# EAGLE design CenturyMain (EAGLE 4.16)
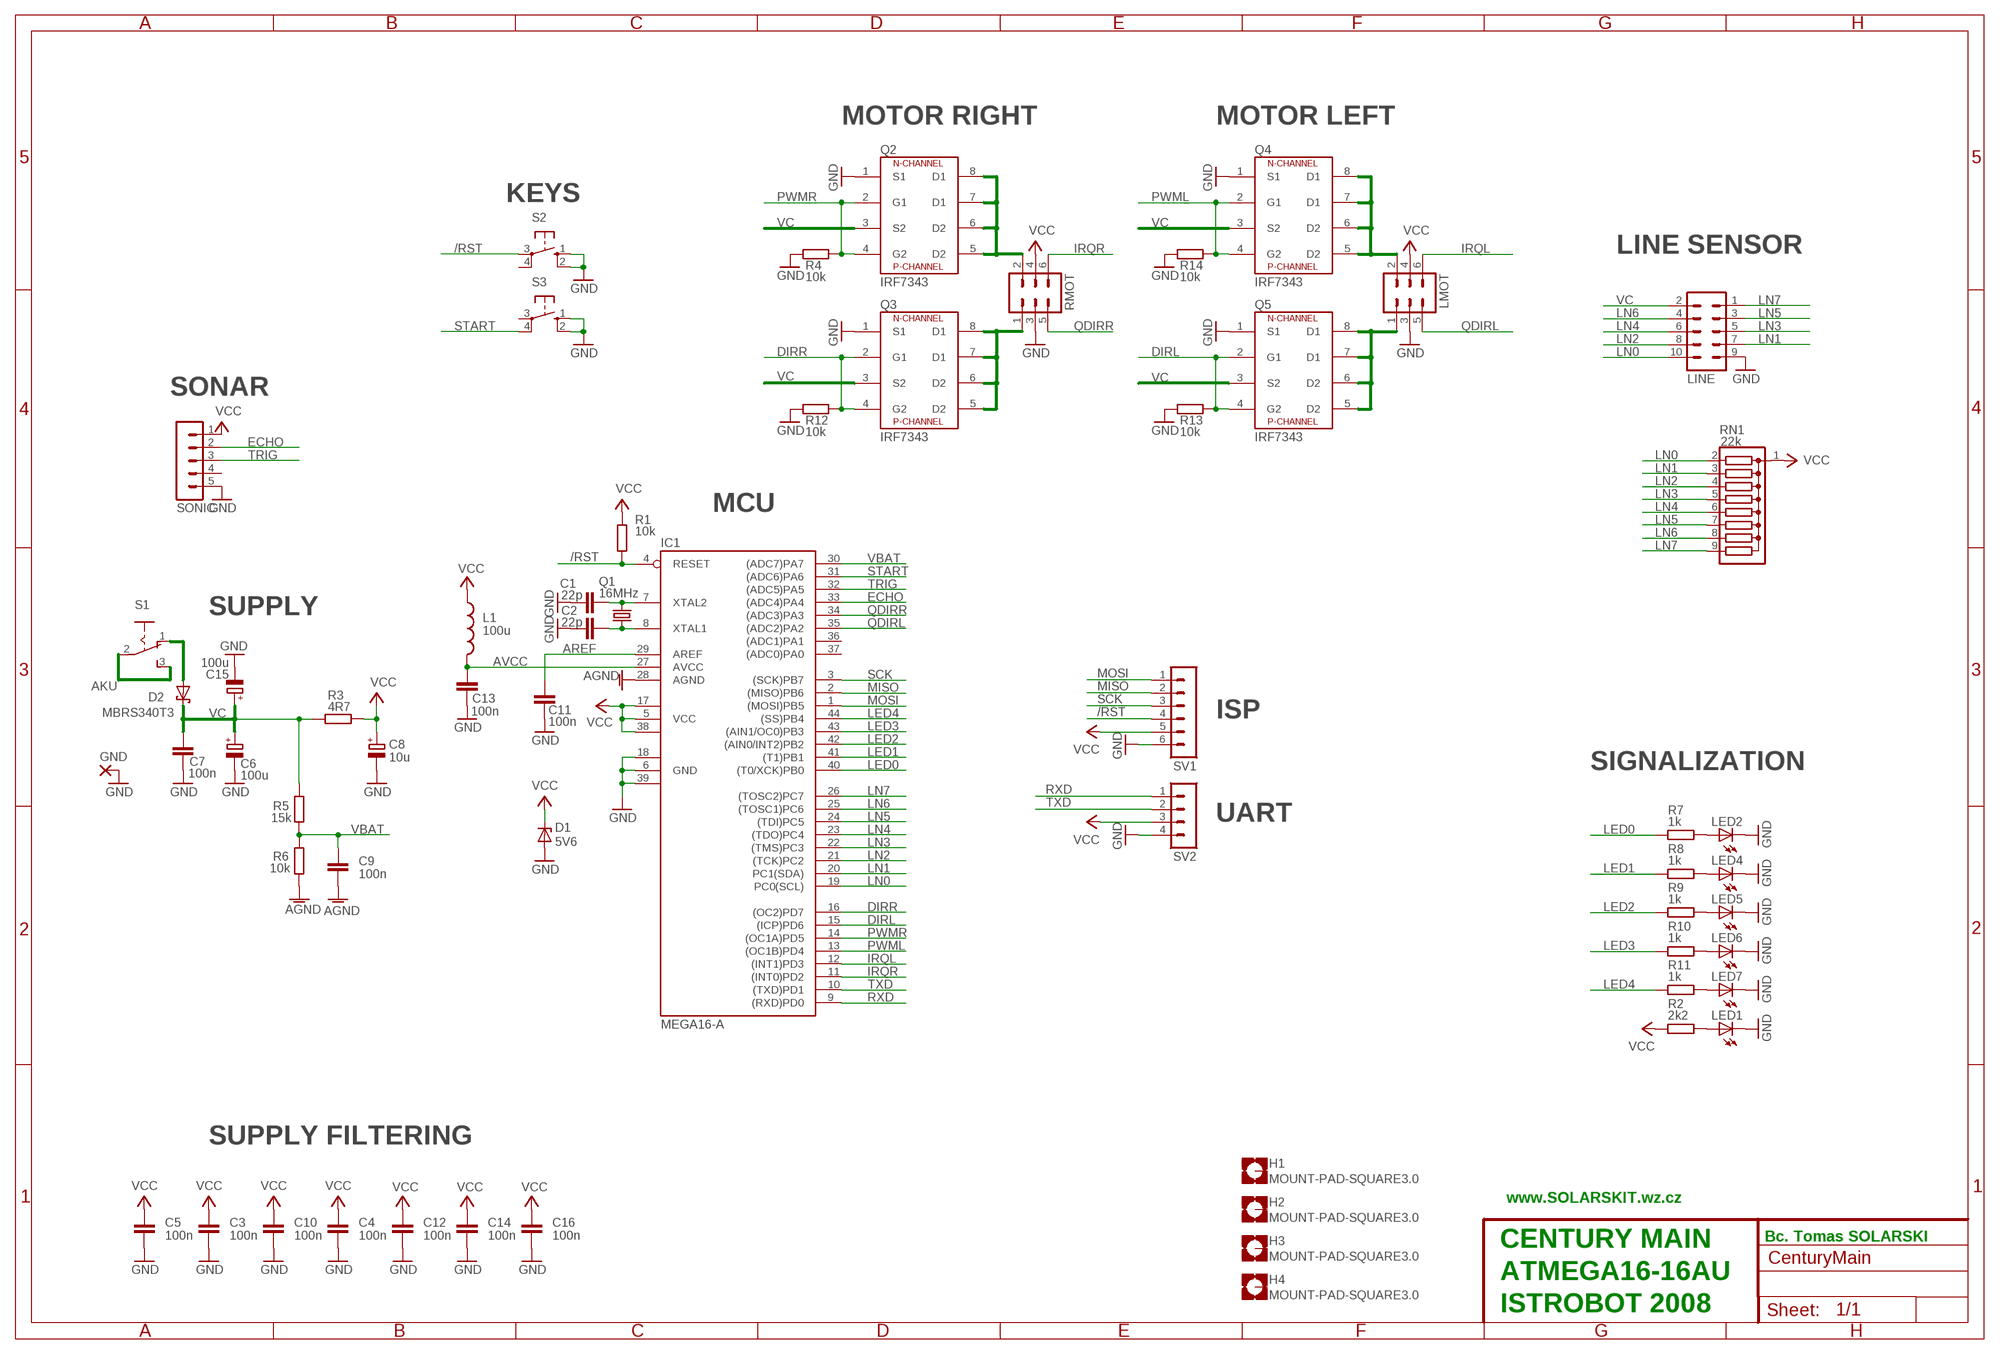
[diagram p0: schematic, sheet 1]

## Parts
C1  22p  C-EUC1206  [C1206]
C2  22p  C-EUC1206  [C1206]
C3  100n  C-EUC1206  [C1206]
C4  100n  C-EUC1206  [C1206]
C5  100n  C-EUC1206  [C1206]
C6  100u  CPOL-EUE5-8.5  [E5-8,5]
C7  100n  C-EUC1206  [C1206]
C8  10u  CPOL-EUB/3528-21W  [B/3528-21W]
C9  100n  C-EUC1206  [C1206]
C10  100n  C-EUC1206  [C1206]
C11  100n  C-EUC1206  [C1206]
C12  100n  C-EUC1206  [C1206]
C13  100n  C-EUC1206  [C1206]
C14  100n  C-EUC1206  [C1206]
C15  100u  CPOL-EUE5-8.5  [E5-8,5]
C16  100n  C-EUC1206  [C1206]
D1  5V6  ZENER-DIODESOD80C  [SOD80C]
D2  MBRS340T3  SCHOTTKY-DIODESMC  [SMC]
GND  SMD5  [SMD5]
H1  MOUNT-PAD-SQUARE3.0  [3,0-PAD-SQUARE]
H2  MOUNT-PAD-SQUARE3.0  [3,0-PAD-SQUARE]
H3  MOUNT-PAD-SQUARE3.0  [3,0-PAD-SQUARE]
H4  MOUNT-PAD-SQUARE3.0  [3,0-PAD-SQUARE]
IC1  MEGA16-A  [TQFP44]
L1  100u  L-US0207/7  [0207/7]
LED1  LEDCHIPLED_1206  [CHIPLED_1206]
LED2  LEDCHIPLED_1206  [CHIPLED_1206]
LED4  LEDCHIPLED_1206  [CHIPLED_1206]
LED5  LEDCHIPLED_1206  [CHIPLED_1206]
LED6  LEDCHIPLED_1206  [CHIPLED_1206]
LED7  LEDCHIPLED_1206  [CHIPLED_1206]
LINE  ML10  [ML10]
LMOT  ML6  [ML6]
Q1  16MHz  CRYSTALHC49S  [HC49/S]
Q2  IRF7343  [SO-8]
Q3  IRF7343  [SO-8]
Q4  IRF7343  [SO-8]
Q5  IRF7343  [SO-8]
R1  10k  R-EU_M1206  [M1206]
R2  2k2  R-EU_M1206  [M1206]
R3  4R7  R-EU_M1206  [M1206]
R4  10k  R-EU_M0805  [M0805]
R5  15k  R-EU_M1206  [M1206]
R6  10k  R-EU_M1206  [M1206]
R7  1k  R-EU_M1206  [M1206]
R8  1k  R-EU_M1206  [M1206]
R9  1k  R-EU_M1206  [M1206]
R10  1k  R-EU_M1206  [M1206]
R11  1k  R-EU_M1206  [M1206]
R12  10k  R-EU_M0805  [M0805]
R13  10k  R-EU_M0805  [M0805]
R14  10k  R-EU_M0805  [M0805]
RMOT  ML6  [ML6]
RN1  22k  G08R  [SIL9]
S1  255SB  [255SB]
S2  10-XX  [B3F-10XX]
S3  10-XX  [B3F-10XX]
SONIC  MA05-1W  [MA08-1W]
SV1  MA06-1  [MA06-1]
SV2  MA04-1  [MA04-1]

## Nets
/RST: IC1.4(RESET) R1.2 S2.3(P) SV1.4
AGND: C9.2 IC1.28(AGND) R6.2
AKU: S1.2(P) S1.3(S)
AREF: C11.1 IC1.29(AREF)
AVCC: C13.1 IC1.27(AVCC) L1.2
DIRL: IC1.15((ICP)PD6) Q5.2(G1) Q5.4(G2) R13.2
DIRR: IC1.16((OC2)PD7) Q3.2(G1) Q3.4(G2) R12.2
ECHO: IC1.33((ADC4)PA4) SONIC.2
GND: C1.1 C2.1 C3.2 C4.2 C5.2 C6.- C7.2 C8.- C10.2 C11.2 C12.2 C13.2 C14.2 C15.- C16.2 D1.A GND.1(P) IC1.6(GND) IC1.18(GND1) IC1.39(GND2) LED1.C LED2.C LED4.C LED5.C LED6.C LED7.C LINE.9 LMOT.3 Q2.1(S1) Q3.1(S1) Q4.1(S1) Q5.1(S1) R4.1 R12.1 R13.1 R14.1 RMOT.3 S2.1(S) S2.2(S1) S3.1(S) S3.2(S1) SONIC.5 SV1.6 SV2.4
IRQL: IC1.12((INT1)PD3) LMOT.6
IRQR: IC1.11((INT0)PD2) RMOT.6
LED0: IC1.40((T0/XCK)PB0) R7.1
LED1: IC1.41((T1)PB1) R8.1
LED2: IC1.42((AIN0/INT2)PB2) R9.1
LED3: IC1.43((AIN1/OC0)PB3) R10.1
LED4: IC1.44((SS)PB4) R11.1
LN0: IC1.19(PC0(SCL)) LINE.10 RN1.2
LN1: IC1.20(PC1(SDA)) LINE.7 RN1.3
LN2: IC1.21((TCK)PC2) LINE.8 RN1.4
LN3: IC1.22((TMS)PC3) LINE.5 RN1.5
LN4: IC1.23((TDO)PC4) LINE.6 RN1.6
LN5: IC1.24((TDI)PC5) LINE.3 RN1.7
LN6: IC1.25((TOSC1)PC6) LINE.4 RN1.8
LN7: IC1.26((TOSC2)PC7) LINE.1 RN1.9
MISO: IC1.2((MISO)PB6) SV1.2
MOSI: IC1.1((MOSI)PB5) SV1.1
N$1: C1.2 IC1.7(XTAL2) Q1.2
N$2: C2.2 IC1.8(XTAL1) Q1.1
N$3: LED1.A R2.2
N$4: Q2.5(D2) Q2.6(D2) Q2.7(D1) Q2.8(D1) RMOT.2
N$6: Q3.5(D2) Q3.6(D2) Q3.7(D1) Q3.8(D1) RMOT.1
N$8: D2.A S1.1(O)
N$9: LMOT.2 Q4.5(D2) Q4.6(D2) Q4.7(D1) Q4.8(D1)
N$10: LMOT.1 Q5.5(D2) Q5.6(D2) Q5.7(D1) Q5.8(D1)
N$11: LED2.A R7.2
N$12: LED4.A R8.2
N$13: LED5.A R9.2
N$14: LED6.A R10.2
N$15: LED7.A R11.2
PWML: IC1.13((OC1B)PD4) Q4.2(G1) Q4.4(G2) R14.2
PWMR: IC1.14((OC1A)PD5) Q2.2(G1) Q2.4(G2) R4.2
QDIRL: IC1.35((ADC2)PA2) LMOT.5
QDIRR: IC1.34((ADC3)PA3) RMOT.5
RXD: IC1.9((RXD)PD0) SV2.1
SCK: IC1.3((SCK)PB7) SV1.3
START: IC1.31((ADC6)PA6) S3.4(P1)
TRIG: IC1.32((ADC5)PA5) SONIC.3
TXD: IC1.10((TXD)PD1) SV2.2
VBAT: C9.1 IC1.30((ADC7)PA7) R5.2 R6.1
VC: C6.+ C7.1 C15.+ D2.C LINE.2 Q2.3(S2) Q3.3(S2) Q4.3(S2) Q5.3(S2) R3.1 R5.1
VCC: C3.1 C4.1 C5.1 C8.+ C10.1 C12.1 C14.1 C16.1 D1.C IC1.5(VCC) IC1.17(VCC1) IC1.38(VCC2) L1.1 LMOT.4 R1.1 R2.1 R3.2 RMOT.4 RN1.1 SONIC.1 SV1.5 SV2.3
Unconnected: H1.B3,0(MOUNT) H2.B3,0(MOUNT) H3.B3,0(MOUNT) H4.B3,0(MOUNT) IC1.36((ADC1)PA1) IC1.37((ADC0)PA0) S2.4(P1) S3.3(P) SONIC.4

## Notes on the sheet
- MOTOR RIGHT | MOTOR LEFT
- KEYS
- LINE SENSOR
- SONAR
- MCU
- SUPPLY
- ISP
- SIGNALIZATION
- UART
- SUPPLY FILTERING
- www.SOLARSKIT.wz.cz
- Bc. Tomas SOLARSKI
- CENTURY MAIN
- ATMEGA16-16AU
- ISTROBOT 2008

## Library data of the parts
C1-C5 C7 C9-C14 C16 = rcl:C-EU: CAPACITOR, European symbol
C6 C8 C15 = rcl:CPOL-EU: POLARIZED CAPACITOR, European symbol
D1 = diode:ZENER-DIODE: Z-Diode
D2 = diode:SCHOTTKY-DIODE: Schottky Diode
GND = wirepad:SMD5: SMD PAD
H1-H4 = holes:MOUNT-PAD-SQUARE: MOUNTING PAD, square
IC1 = atmel:MEGA16: MICROCONTROLLER 16 Kbytes FLASH 1 kbytes SRAM 512 bytes EEPROM USART 8-channel 10 bit ADC Source: avr.lbr
L1 = rcl:L-US: INDUCTOR, American symbol
LED1 LED2 LED4-LED7 = led:LED: LED
LINE = con-harting-ml:ML10: HARTING
LMOT RMOT = con-harting-ml:ML6: HARTING
Q1 = crystal:CRYSTAL: CRYSTAL
Q2-Q5 = !_IRF7343:IRF7343
R1-R14 = rcl:R-EU_: RESISTOR, European symbol
RN1 = resistor-sil:G08R: SIL RESISTOR
S1 = switch:255SB: SLIDING SWITCH distributor Buerklin, 11G810
S2 S3 = switch-omron:10-XX: OMRON SWITCH
SONIC = 0_MA05-1W:MA05-1W
SV1 = con-lstb:MA06-1: PIN HEADER
SV2 = con-lstb:MA04-1: PIN HEADER

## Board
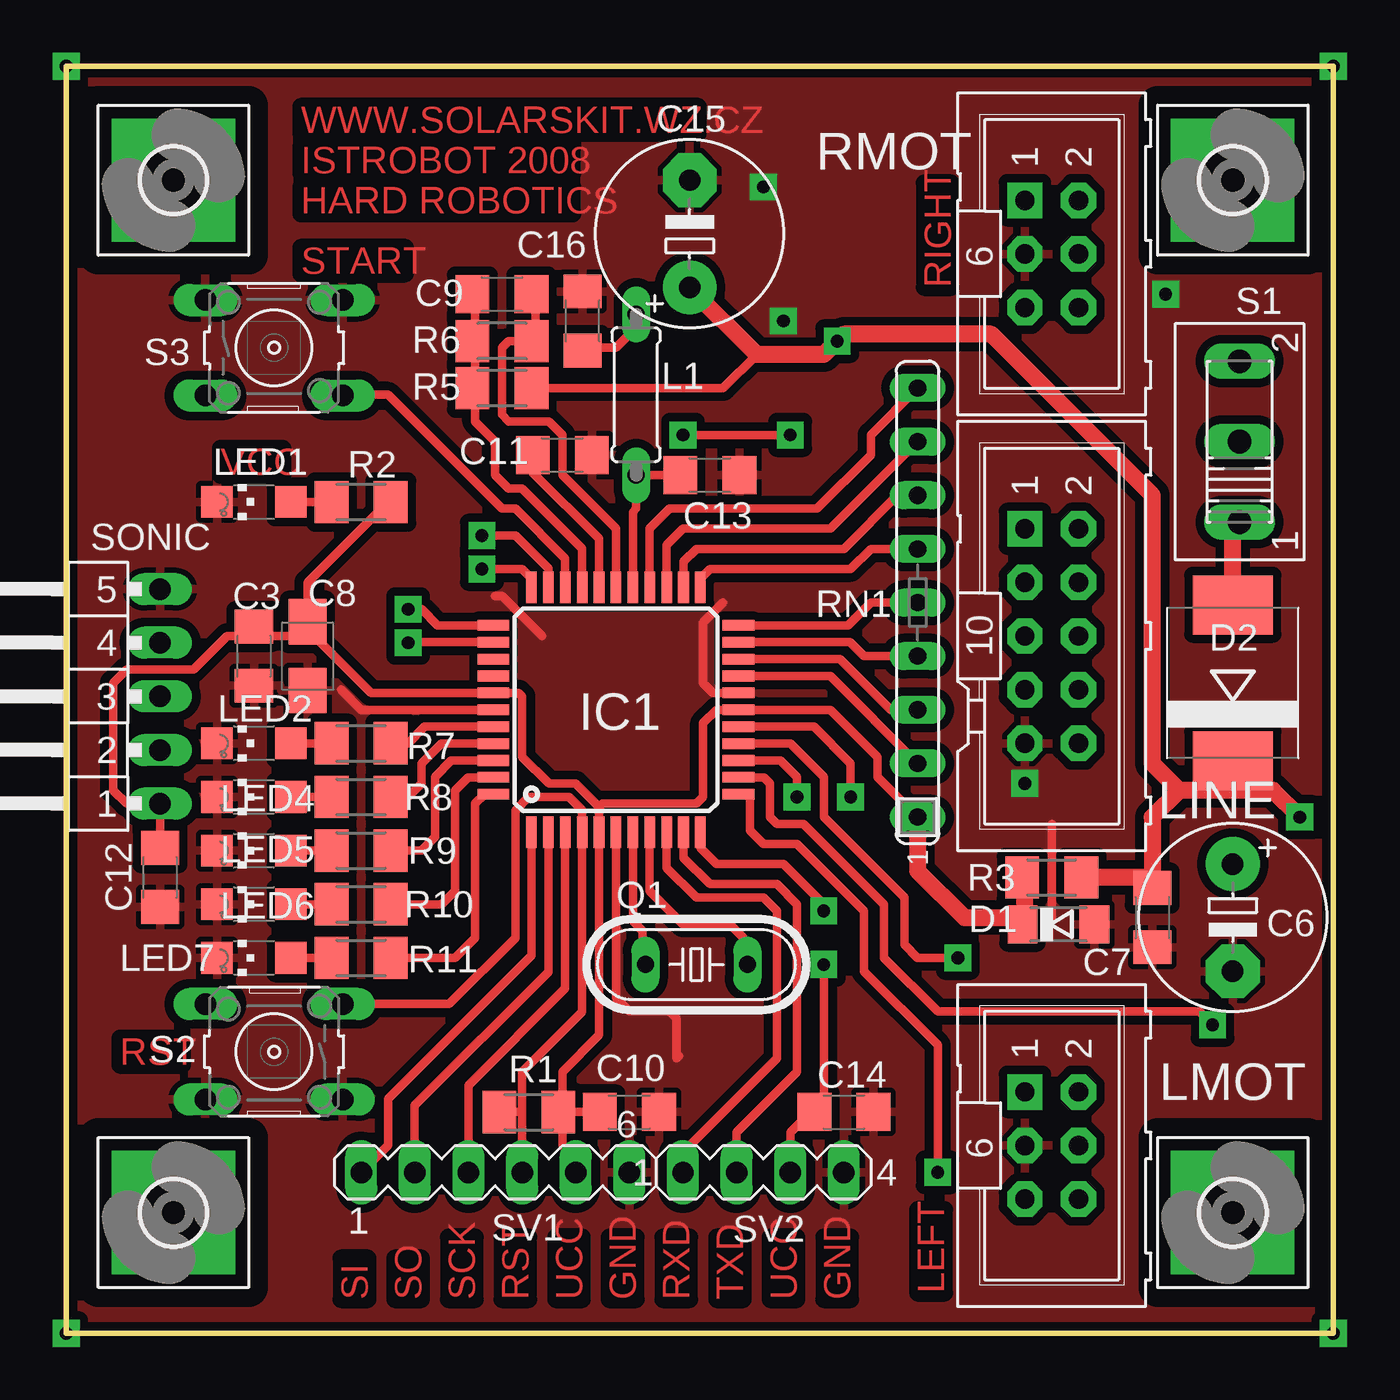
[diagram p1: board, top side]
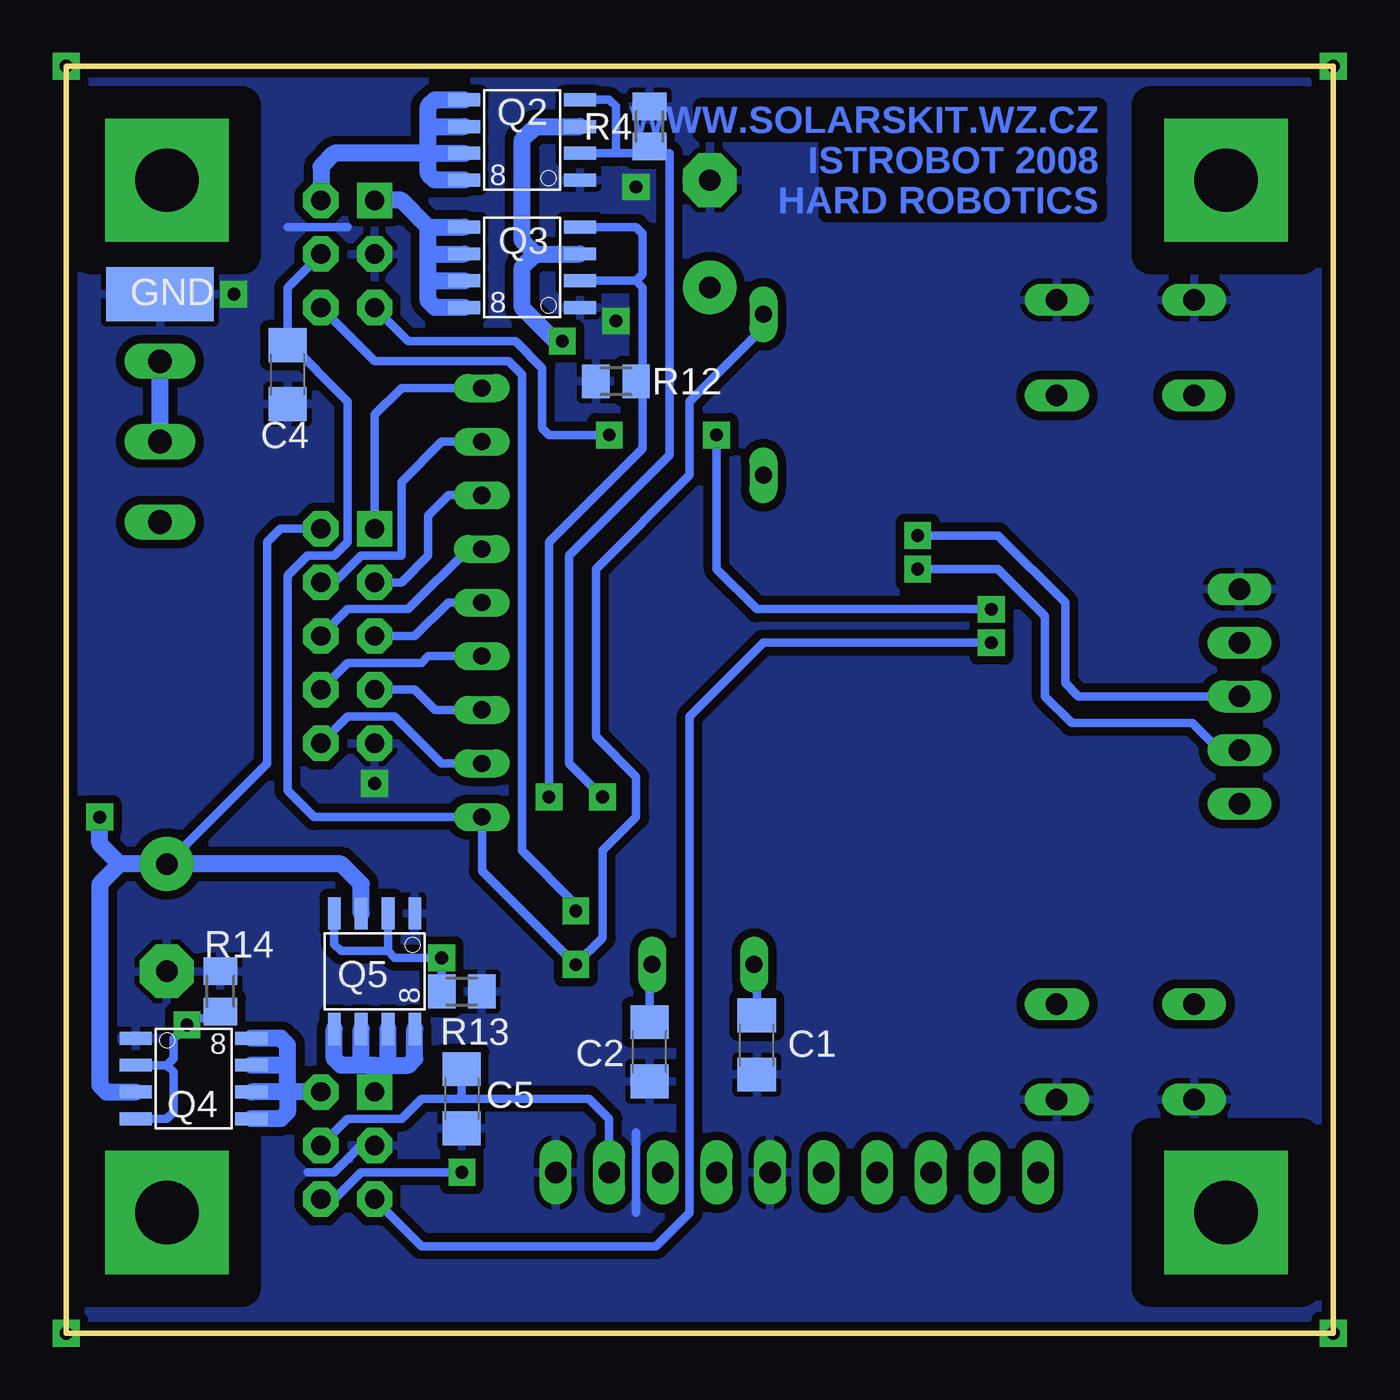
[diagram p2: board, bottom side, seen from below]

Size 60.01 x 60.01 mm. Coordinates in mm from the lower left corner, seen from the top.
Outline: 0,0 60.01,0 60.01,60.01 0,60.01 0,0
Copper layers (1*16): Top 0.035mm / dielectric 1.5mm / Bottom 0.035mm
Design rules "default": minimum track width 10mil, minimum drill 0.6mm, track to track 8mil, track to pad 8mil, pad to pad 8mil, via to via 8mil, smd to smd 8mil, copper to edge 16mil, drill to drill 8mil, minimum pad ring 10mil, minimum via ring 8mil, stop-mask expansion 4mil, vias tented up to drill 0mil, thermal gap 10mil

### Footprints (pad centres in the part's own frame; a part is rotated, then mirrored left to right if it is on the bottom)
C1206 = smd 1.6 x 1.8: 1 -1.4,0; 2 1.4,0
E5-8,5 = drill 1.016 pad 2.54 round: + -2.54,0 | drill 1.016 pad 2.54 octagon: - 2.54,0
B/3528-21W = smd 2.15 x 1.8: + 1.625,0; - -1.625,0
SOD80C = smd 1.4 x 1.8: A 1.7,0; C -1.7,0
SMC = smd 2.8 x 3.8: A 3.7,0; C -3.7,0
SMD5 = smd 2.54 x 5.08: 1 0,0
3,0-PAD-SQUARE = drill 3 pad 5.842 square: B3,0 0,0
TQFP44 = smd 1.5 x 0.5: 1 -5.8,4; 2 -5.8,3.2; 3 -5.8,2.4; 4 -5.8,1.6; 5 -5.8,0.8; 6 -5.8,0; 7 -5.8,-0.8; 8 -5.8,-1.6; 9 -5.8,-2.4; 10 -5.8,-3.2; 11 -5.8,-4; 23 5.8,-4; 24 5.8,-3.2; 25 5.8,-2.4; 26 5.8,-1.6; 27 5.8,-0.8; 28 5.8,0; 29 5.8,0.8; 30 5.8,1.6; 31 5.8,2.4; 32 5.8,3.2; 33 5.8,4 | smd 0.5 x 1.5: 12 -4,-5.8; 13 -3.2,-5.8; 14 -2.4,-5.8; 15 -1.6,-5.8; 16 -0.8,-5.8; 17 0,-5.8; 18 0.8,-5.8; 19 1.6,-5.8; 20 2.4,-5.8; 21 3.2,-5.8; 22 4,-5.8; 34 4,5.8; 35 3.2,5.8; 36 2.4,5.8; 37 1.6,5.8; 38 0.8,5.8; 39 0,5.8; 40 -0.8,5.8; 41 -1.6,5.8; 42 -2.4,5.8; 43 -3.2,5.8; 44 -4,5.8
0207/7 = drill 0.813 long: 1 -3.81,0; 2 3.81,0
CHIPLED_1206 = smd 1.5 x 1.5: A 0,-1.75; C 0,1.75
ML10 = drill 0.914 pad 1.676 square: 1 -5.08,-1.27 | drill 0.914 pad 1.676 octagon: 2 -5.08,1.27; 3 -2.54,-1.27; 4 -2.54,1.27; 5 0,-1.27; 6 0,1.27; 7 2.54,-1.27; 8 2.54,1.27; 9 5.08,-1.27; 10 5.08,1.27
ML6 = drill 0.914 pad 1.676 square: 1 -2.54,-1.27 | drill 0.914 pad 1.676 octagon: 2 -2.54,1.27; 3 0,-1.27; 4 0,1.27; 5 2.54,-1.27; 6 2.54,1.27
HC49/S = drill 0.813 long: 1 -2.413,0; 2 2.413,0
SO-8 = smd 1.524 x 0.61: 1 -2.743,1.27; 2 -2.743,0; 3 -2.743,-1.27; 4 -2.743,-2.54; 5 2.743,-2.54; 6 2.743,-1.27; 7 2.743,0; 8 2.743,1.27
M1206 = smd 1.6 x 2: 1 -1.4,0; 2 1.4,0
M0805 = smd 1.3 x 1.6: 1 -0.95,0; 2 0.95,0
SIL9 = drill 0.813 long: 1 -10.16,0; 2 -7.62,0; 3 -5.08,0; 4 -2.54,0; 5 0,0; 6 2.54,0; 7 5.08,0; 8 7.62,0; 9 10.16,0
255SB = drill 1.118 long: 1 -3.81,0; 2 0,0; 3 3.81,0
B3F-10XX = drill 1.016 long: 1 -3.251,2.261; 2 3.251,2.261; 3 -3.251,-2.261; 4 3.251,-2.261
MA08-1W = drill 1.016 long: 1 -8.89,0; 2 -6.35,0; 3 -3.81,0; 4 -1.27,0; 5 1.27,0
MA06-1 = drill 1.016 long: 1 -6.35,0; 2 -3.81,0; 3 -1.27,0; 4 1.27,0; 5 3.81,0; 6 6.35,0
MA04-1 = drill 1.016 long: 1 -3.81,0; 2 -1.27,0; 3 1.27,0; 4 3.81,0

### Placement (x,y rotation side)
C1  27.3,13.65 90 bottom
C2  32.38,13.34 90 bottom
C3  8.89,32.07 270 top
C4  49.53,45.4 270 bottom
C5  41.27,11.11 270 bottom
C6  55.24,19.69 270 top
C7  51.43,19.69 270 top
C8  11.43,32.07 90 top
C9  20.64,49.21 0 top
C10  26.67,10.48 0 top
C11  23.49,41.59 0 top
C12  4.45,21.59 270 top
C13  30.48,40.64 0 top
C14  36.83,10.48 0 top
C15  29.53,52.07 90 top
C16  24.45,47.94 90 top
D1  46.99,19.37 0 top
D2  55.24,30.8 90 top
GND  55.56,49.21 270 bottom
H1  5.08,5.71 0 top
H2  55.24,5.71 0 top
H3  5.08,54.61 0 top
H4  55.24,54.61 0 top
IC1  26.03,29.53 90 top
L1  26.99,44.45 270 top
LED1  8.89,39.37 90 top
LED2  8.89,27.94 90 top
LED4  8.89,25.4 90 top
LED5  8.89,22.86 90 top
LED6  8.89,20.32 90 top
LED7  8.89,17.78 90 top
LINE  46.67,33.02 270 top
LMOT  46.67,8.89 270 top
Q1  29.84,17.46 180 top
Q2  38.42,55.88 180 bottom
Q3  38.42,49.85 180 bottom
Q4  53.98,12.7 0 bottom
Q5  44.77,17.14 270 bottom
R1  21.91,10.48 180 top
R2  13.97,39.37 180 top
R3  46.67,21.59 180 top
R4  32.38,57.15 270 bottom
R5  20.64,44.77 180 top
R6  20.64,46.99 0 top
R7  13.97,27.94 180 top
R8  13.97,25.4 180 top
R9  13.97,22.86 180 top
R10  13.97,20.32 180 top
R11  13.97,17.78 180 top
R12  33.97,45.09 0 bottom
R13  41.27,16.19 180 bottom
R14  52.7,16.19 270 bottom
RMOT  46.67,51.12 270 top
RN1  40.32,34.61 90 top
S1  55.56,42.23 90 top
S2  9.84,13.34 180 top
S3  9.84,46.67 0 top
SONIC  4.45,33.97 90 top
SV1  20.32,7.62 0 top
SV2  33.02,7.62 0 top

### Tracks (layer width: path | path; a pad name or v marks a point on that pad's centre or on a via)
/RST
  Top 0.406: 21.59,10.48 SV1.4 | 21.59,10.48 21.59,12.38 24.44,15.23 IC1.4 24.44,24.78 23.81,25.4 21.91,25.4 21.27,24.77 21.27,18.73 18.14,15.6 S2.3 | 21.59,10.48 R1.2
AGND
  Top 0.406: IC1.28 26.03,38.1 23.49,40.64 23.49,42.55 22.86,43.18 20.95,43.18 20.64,43.5 20.64,46.67 20.95,46.99 21.91,46.99 | C9.2 22.23,49.21 22.23,47.31 21.91,46.99 | 21.91,46.99 R6.2
AKU
  Bottom 0.813: S1.2 S1.3
AREF
  Top 0.406: IC1.29 25.23,37.63 22.09,40.77 C11.1
AVCC
  Top 0.406: IC1.27 26.84,38.9 26.99,39.05 L1.2 C13.1 29.21,40.64
DIRL  (via drill 0.6 pad 1.27)
  Top 0.406: v42.23,17.78 40.32,17.78 39.69,18.41 39.69,20.64 35.88,24.45 35.88,26.35 34.3,27.93 IC1.15
  Bottom 0.406: Q5.4 47.31,18.41 46.99,18.1 44.77,18.1 | 44.77,18.1 Q5.2 | 44.77,18.1 44.45,17.78 v42.23,17.78 R13.2
DIRR  (via drill 0.6 pad 1.27)
  Top 0.406: IC1.16 35.41,28.73 37.15,26.99 v37.15,25.4
  Bottom 0.406: v37.15,25.4 37.15,37.46 32.7,41.91 32.7,45.09 | 32.7,45.09 32.7,49.53 33.02,49.85 | 33.02,49.85 Q3.2 | Q3.4 33.02,52.39 32.7,52.07 32.7,50.16 33.02,49.85 | 32.7,45.09 R12.2
ECHO  (via drill 0.6 pad 1.27)
  Top 0.406: v19.69,36.2 21.59,36.2 22.03,35.75 IC1.33
  Bottom 0.406: SONIC.2 5.4,27.62 6.67,28.89 12.38,28.89 13.65,30.16 13.65,33.97 15.88,36.2 v19.69,36.2
GND  (via drill 0.6 pad 1.27)
  Top 0.406: IC1.18 30.63,30.33 30.16,30.8 30.16,33.66 31.12,34.61 | 46.67,19.69 46.67,24.13 | 20.32,34.92 20.64,34.92 22.54,33.02 | IC1.6 26.03,15.88 26.67,15.24 28.58,15.24 28.89,14.92 28.89,13.02 29.02,13.15 | IC1.39 13.97,29.53 13.02,30.48
  Bottom 0.406: 46.67,52.39 49.53,52.39 | LMOT.3 46.04,8.89 47.31,7.62 48.58,7.62 | 33.02,5.71 33.02,9.53
  other vias: 33.02,54.29 33.97,47.94 52.07,49.21 45.4,26.03
  pour Top (isolate 0.406, rank 2): -0.63,-0.63 63.18,-0.63 63.18,60.64 -0.63,60.64
  pour Bottom (isolate 0.406): 60.64,-0.63 -3.49,-0.63 -3.49,60.64 60.64,60.64
IRQL  (via drill 0.6 pad 1.27)
  Top 0.406: IC1.12 32.26,25.53 32.38,25.4 32.38,23.81 33.02,23.18 34.61,23.18 37.78,20 37.78,17.14 41.27,13.65 v41.27,7.62
  Bottom 0.406: v41.27,7.62 46.04,7.62 47.31,6.35 LMOT.6
IRQR  (via drill 0.6 pad 1.27)
  Top 0.406: IC1.11 30.03,22.99 30.8,22.23 33.97,22.23 35.88,20.32 v35.88,20
  Bottom 0.406: RMOT.6 45.4,46.04 39.05,46.04 38.42,45.4 38.42,22.86 35.88,20.32 v35.88,20
LED0
  Top 0.406: IC1.40 16.98,28.73 16.19,27.94 R7.1
LED1
  Top 0.406: IC1.41 17.77,27.93 16.83,26.99 16.83,26.03 16.19,25.4 R8.1
LED2
  Top 0.406: IC1.42 18.24,27.13 17.46,26.35 17.46,23.49 16.83,22.86 R9.1
LED3
  Top 0.406: IC1.43 19.02,26.33 18.41,25.72 18.41,20.95 17.78,20.32 R10.1
LED4
  Top 0.406: IC1.44 19.81,25.53 19.37,25.08 19.37,18.73 18.41,17.78 R11.1
LN0
  Top 0.406: IC1.19 36.18,31.13 RN1.2
  Bottom 0.406: RN1.2 42.23,26.99 44.45,29.21 46.67,29.21 LINE.10
LN1
  Top 0.406: IC1.20 36.65,31.93 39.05,29.53 RN1.3
  Bottom 0.406: RN1.3 42.55,29.53 43.5,30.48 LINE.7
LN2
  Top 0.406: IC1.21 37.12,32.73 37.78,32.07 RN1.4
  Bottom 0.406: RN1.4 42.86,32.07 43.18,31.75 46.67,31.75 LINE.8
LN3
  Top 0.406: IC1.22 37.02,33.53 38.1,34.61 RN1.5
  Bottom 0.406: RN1.5 41.91,34.61 43.5,33.02 LINE.5
LN4
  Top 0.406: IC1.23 30.03,35.75 30.48,36.2 37.15,36.2 38.1,37.15 RN1.6
  Bottom 0.406: RN1.6 40.96,37.15 43.81,34.29 46.67,34.29 LINE.6
LN5
  Top 0.406: IC1.24 29.23,36.54 29.84,37.15 36.83,37.15 39.37,39.69 RN1.7
  Bottom 0.406: RN1.7 41.91,39.69 42.86,38.73 42.86,36.83 44.13,35.56 LINE.3
LN6
  Top 0.406: IC1.25 28.44,37.32 29.21,38.1 36.2,38.1 RN1.8
  Bottom 0.406: RN1.8 42.23,42.23 44.13,40.32 44.13,36.83 46.04,36.83 47.31,35.56 LINE.4
LN7
  Top 0.406: IC1.26 27.63,38.11 28.58,39.05 35.56,39.05 38.1,41.59 38.1,42.55 RN1.9
  Bottom 0.406: RN1.9 44.13,44.77 45.4,43.5 LINE.1
MISO
  Top 0.406: SV1.2 16.51,10.79 22.84,17.12 IC1.2
MOSI
  Top 0.406: IC1.1 22.03,17.91 15.24,11.11 15.24,8.89 SV1.1
N$1
  Top 0.406: IC1.7 26.84,19.52 27.3,19.05 27.3,17.46 Q1.2
  Bottom 0.406: C1.2 27.3,17.14 27.43,17.27 Q1.2
N$2
  Top 0.406: IC1.8 27.63,20.94 29.21,19.37 31.43,19.37 32.07,18.73 32.07,17.46 Q1.1
  Bottom 0.406: Q1.1 32.26,17.27 32.38,17.14 C2.2
N$3
  Top 0.406: LED1.A R2.2
N$4
  Bottom 0.813: Q2.5 42.55,58.42 42.86,58.1 42.86,57.15 | Q2.8 42.55,54.61 42.86,54.93 42.86,55.88 | 42.86,55.88 42.86,57.15 | 42.86,57.15 Q2.6 | 42.86,55.88 Q2.7 | RMOT.2 47.94,55.24 47.31,55.88 42.86,55.88
N$5  (via drill 0.6 pad 1.27)
  other vias: 0,60.01
N$6
  Bottom 0.813: Q3.8 42.55,48.58 42.86,48.89 42.86,49.85 | 42.86,49.85 42.86,51.12 | 42.86,51.12 42.86,52.39 | 42.86,49.85 Q3.7 | 42.86,51.12 Q3.6 | 42.86,52.39 Q3.5 | 42.86,52.39 44.13,53.66 RMOT.1
N$7  (via drill 0.6 pad 1.27)
  other vias: 0,0
N$8
  Top 0.813: S1.1 55.24,38.1 D2.A
N$9
  Bottom 0.813: Q4.8 49.85,13.97 49.53,13.65 49.53,12.7 | 49.53,11.43 49.53,10.48 49.85,10.16 Q4.5 | 49.53,11.43 49.53,12.7 | 49.53,11.43 Q4.6 | 49.53,12.7 Q4.7 | LMOT.2 49.53,11.43
N$10
  Bottom 0.813: Q5.8 43.5,13.02 43.81,12.7 44.77,12.7 | 45.4,12.7 44.77,12.7 | 45.4,12.7 46.04,12.7 | 46.04,12.7 46.99,12.7 47.31,13.02 Q5.5 | 44.77,12.7 Q5.7 | 46.04,12.7 Q5.6 | LMOT.1 45.4,12.7
N$11
  Top 0.406: 12.7,27.94 R7.2 LED2.A
N$12
  Top 0.406: LED4.A R8.2
N$13
  Top 0.406: 12.7,22.86 R9.2 LED5.A
N$14
  Top 0.406: LED6.A R10.2
N$15
  Top 0.406: LED7.A R11.2
N$16  (via drill 0.6 pad 1.27)
  other vias: 60.01,0
N$17  (via drill 0.6 pad 1.27)
  other vias: 60.01,60.01
PWML  (via drill 0.6 pad 1.27)
  Top 0.406: v54.29,14.61 53.66,15.24 41.27,15.24 38.73,17.78 38.73,20.32 34.92,24.13 33.66,24.13 33.34,24.45 33.34,26.03 33.05,26.33 IC1.13
  Bottom 0.406: Q4.4 55.24,10.16 54.93,10.48 54.93,12.38 55.24,12.7 | 55.24,12.7 Q4.2 | 55.24,12.7 54.93,13.02 54.93,13.97 v54.29,14.61 54.29,14.92 52.7,14.92 R14.2
PWMR  (via drill 0.6 pad 1.27)
  Top 0.406: IC1.14 33.83,27.13 34.61,26.35 v34.61,25.4
  Bottom 0.406: Q2.4 34.29,58.42 33.97,58.1 33.97,55.88 | 33.97,55.88 Q2.2 | 32.38,55.88 31.43,55.88 31.43,41.59 36.2,36.83 36.2,26.99 v34.61,25.4 | 32.38,55.88 33.97,55.88 | 32.38,55.88 R4.2
QDIRL  (via drill 0.6 pad 1.27)
  Top 0.406: v16.19,32.7 16.22,32.73 IC1.35
  Bottom 0.406: LMOT.5 43.18,4.13 32.07,4.13 30.48,5.71 30.48,29.21 26.99,32.7 v16.19,32.7
QDIRR  (via drill 0.6 pad 1.27)
  Top 0.406: v16.19,34.29 16.83,34.29 17.59,33.53 IC1.34 | v29.21,42.55 v34.29,42.55
  Bottom 0.406: v34.29,42.55 37.15,42.55 37.46,42.86 37.46,45.72 38.73,46.99 43.81,46.99 RMOT.5 | v16.19,34.29 27.3,34.29 29.21,36.2 v29.21,42.55
RXD
  Top 0.406: IC1.9 28.44,22.05 29.84,20.64 33.02,20.64 33.66,20 33.66,13.02 29.21,8.57 SV2.1
SCK
  Top 0.406: IC1.3 23.63,16.33 19.05,11.75 SV1.3
START
  Top 0.406: IC1.31 23.63,36.69 21.27,39.05 20.64,39.05 15.24,44.45 13.02,44.45 13.06,44.41 S3.4
TRIG  (via drill 0.6 pad 1.27)
  Top 0.406: v19.69,37.78 21.27,37.78 22.84,36.22 IC1.32
  Bottom 0.406: SONIC.3 12.07,30.16 12.7,30.8 12.7,34.61 15.88,37.78 v19.69,37.78
TXD
  Top 0.406: IC1.10 29.23,22.52 30.48,21.27 33.66,21.27 34.61,20.32 34.61,12.38 31.75,9.53 SV2.2
VBAT
  Top 0.406: IC1.30 24.44,37.16 21.59,40 20.95,40 20.32,40.64 20.32,42.23 19.37,43.18 19.37,44.77 | 19.37,44.77 R5.2 | 19.37,44.77 19.37,46.67 19.24,46.8 R6.1 19.37,46.99 19.37,49.21 C9.1
VC  (via drill 0.6 pad 1.27)
  Top 0.406: 55.24,25.72 55.24,26.03 | R5.1 31.12,44.77 32.7,46.35
  Top 0.813: v58.42,24.45 57.15,25.72 55.24,25.72 | 55.24,25.72 55.13,25.83 | 51.43,21.59 R3.1 | 51.43,21.59 C7.1 | 52.7,25.72 51.43,26.99 51.43,39.69 43.81,47.31 36.83,47.31 v36.51,46.99 35.88,46.35 32.7,46.35 C15.+ | 55.24,25.72 D2.C | 55.24,25.72 52.7,25.72 | 52.7,25.72 51.43,24.45 51.43,21.59
  Bottom 0.406: LINE.2 49.85,38.1 50.48,37.46 50.48,26.99 C6.+
  Bottom 0.813: Q2.3 37.78,57.15 38.42,56.52 38.42,51.75 37.78,51.12 | 37.78,51.12 Q3.3 | v58.42,24.45 58.42,23.18 57.47,22.23 | 57.47,22.23 C6.+ 46.99,22.23 46.04,21.27 Q5.3 | 57.47,22.23 58.42,21.27 58.42,11.75 58.1,11.43 Q4.3 | v36.51,46.99 36.83,46.99 38.42,48.58 38.42,50.48 37.78,51.12
VCC  (via drill 0.6 pad 1.27)
  Top 0.406: RN1.1 38.42,26.35 38.42,27.3 36.2,29.53 IC1.17 30.8,29.53 30.16,28.89 30.16,25.4 29.84,25.08 25.4,25.08 25.25,24.93 25.23,24.93 | 25.23,24.93 IC1.5 25.23,14.12 23.49,12.38 23.49,10.48 | 25.23,24.93 24.13,26.03 22.86,26.03 21.59,27.3 21.59,30.16 21.42,30.33 IC1.38 14.44,30.33 11.75,33.02 11.43,33.02 | v35.88,17.46 35.88,11.11 35.4,10.64 | 35.4,10.64 34.29,9.53 SV2.3 | 8.89,33.02 11.43,33.02 | 8.89,33.02 7.62,33.02 6.03,31.43 2.86,31.43 2.22,30.8 2.22,25.72 2.86,25.08 SONIC.1 C12.1 | 8.89,33.02 C3.1 | 11.43,33.02 11.43,33.66 | 11.43,33.66 C8.+ | 11.43,33.66 11.43,35.56 15.24,39.37 R2.1 | 23.49,10.48 C10.1 | 23.49,10.48 R1.1 23.31,10.35 23.49,10.16 23.49,8.89 24.13,8.25 SV1.5 | 35.4,10.64 35.56,10.48 C14.1 | 35.4,10.64 | C16.1 24.45,46.67 26.03,46.67 26.99,47.62 L1.1
  Top 0.813: 45.4,19.69 45.4,21.59 R3.2 | D1.C 45.4,19.37 45.4,19.69 | 45.4,19.69 42.55,19.69 40.32,21.91 RN1.1
  Bottom 0.406: RMOT.4 49.53,49.53 49.53,46.99 | LMOT.4 46.67,10.16 44.13,10.16 43.18,11.11 41.27,11.11 | 41.27,11.11 35.24,11.11 34.29,10.16 SV2.3 | L1.1 26.99,47.62 30.48,44.13 30.48,40.64 34.92,36.2 34.92,28.26 33.02,26.35 33.02,24.45 34.61,22.86 34.61,18.73 v35.88,17.46 40.32,21.91 RN1.1 48.26,24.45 49.53,25.72 49.53,35.88 48.58,36.83 47.31,36.83 46.67,37.46 46.67,44.13 49.53,46.99 | 49.53,46.99 C4.1 | 41.27,11.11 C5.1

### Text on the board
Top: WWW.SOLARSKIT.WZ.CZ | ISTROBOT 2008 | HARD ROBOTICS | START | RIGHT | VCC | RST | SI | SO | SCK | RST | UCC | GND | RXD | TXD | UCC | GND | LEFT
Bottom: WWW.SOLARSKIT.WZ.CZ | ISTROBOT 2008 | HARD ROBOTICS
